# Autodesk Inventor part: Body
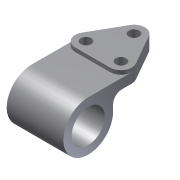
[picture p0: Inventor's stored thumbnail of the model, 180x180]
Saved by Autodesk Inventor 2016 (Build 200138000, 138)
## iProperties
Created: 2010-03
Part Number: Body
Document SubType Name: Modeling
Designer: bhakira
Density: 1 g/cm^3
Material: Generic
Appearance: Default
Author: bhakira
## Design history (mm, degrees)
sketch "Sketch1"
  geometry: L1 (10.853, 41.202)-(30.853, 6.202); L2 (-10.853, 41.202)-(-30.853, 6.202); L3 (-20, -12.5)-(20, -12.5); C1 r 6 at (0, 35); A1 r 12.5 centre (0, 35) between (10.853, 41.202) and (-10.853, 41.202); A2 r 12.5 centre (-20, 0) between (-30.853, 6.202) and (-20, -12.5); A3 r 12.5 centre (20, 0) between (20, -12.5) and (30.853, 6.202); 1 further point
  constraints: 6 end point, 6 point on circle, 6 tangent, 4 centre point, 3 horizontal alignment, 2 equal radius, 1 coincident, 1 vertical alignment, 1 other
  dimensions: "d25" = 35 vertical distance of A1.centre A2.centre; "d27" = 12.5 radius of A1; "d28" = 40 distance of A3.centre A2.centre; "d29" = 20 horizontal distance of A3.centre A1.centre
extrude "Extrusion1" new body sketch "Sketch1" distance "d6" = 15.875; taper "d7" = 0 deg
workplane "Work Plane2"
workplane "Work Plane3"
sketch "Sketch2"
  geometry: L1 (0, 11.375)-(0, 0); L2 (-12.5, 15.875)-(6.202, 15.875) reference; L3 (-50, 11.375)-(0, 11.375); L4 (0, 0)-(-11.5, 0); L5 (-21.5, -17.125)-(-21.5, -10); C1 r 19 at (-50, -17.125); A1 r 28.5 centre (-50, -17.125) between (-50, 11.375) and (-21.5, -17.125); A2 r 10 centre (-11.5, -10) between (-11.5, 0) and (-21.5, -10)
  constraints: 8 end point, 4 point on circle, 4 tangent, 3 centre point, 1 coincident, 1 perpendicular
  dimensions: "d9" = 38 diameter of C1; "d10" = 57 diameter of A1; "d11" = 50 distance from line of L1 C1.centre; "d12" = 33 distance from line of C1.centre L2; "d13" = 10 radius of A2
extrude "Extrusion2" join sketch "Sketch2" stored distance "d14" = 63.5; taper "d15" = 0 deg
sketch "Sketch3"
  geometry: C1 r 6 at (20, 0) reference; C2 r 6 at (-20, 0) reference; C3 r 6 at (0, 35); 1 further point
  constraints: 1 centre point
extrude "Extrusion3" cut sketch "Sketch3" distance "d16" = 63.5; taper "d17" = 0 deg
node "Sketch4"
hole "Hole1" diameter "d32" = 12; stored, may be unused: countersink angle "d36" = 90 deg, drill point angle "d38" = 118 deg; dims "d33" = 6, "d34" = 4, "d35" = 2082.8, "d37" = 8, "d39" = 10, "d40" = 10
body "Solid1"
